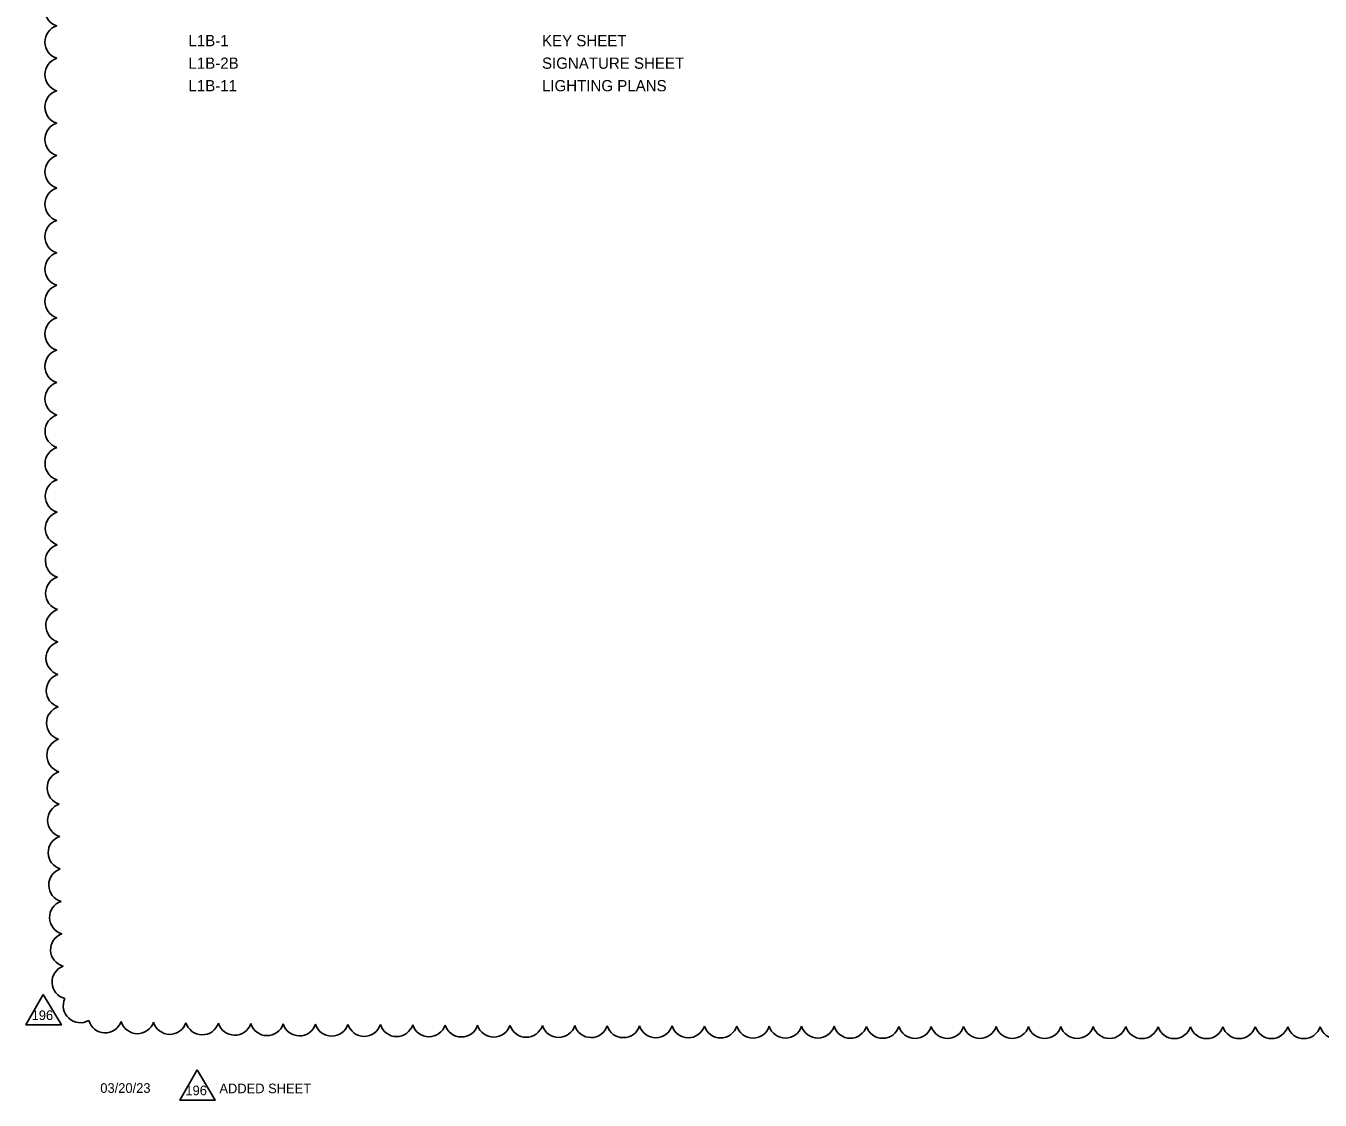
# Model space of a CAD drawing. Extents: x -811.2 to -795, y -2307.6 to -2235.1.
# Drawn here: x -811.23 to -803.18, y -2270.05 to -2263.37 of the extents above; entities that cross this region are included whole.
import ezdxf

# ---------------------------------------------------------------- set-up
doc = ezdxf.new("R2010")
doc.units = 0
for name, color, linetype in [('Cloud_dp', 7, 'Continuous'), ('TeleMisc', 7, 'Continuous'), ('TextMinor', 7, 'Continuous')]:
    doc.layers.add(name, color=color, linetype=linetype)

msp = doc.modelspace()

# ---------------------------------------------------------------- linework, layer by layer
at = {"layer": 'Cloud_dp'}
for points in [[(-811.1249, -2269.3954), (-811.2327, -2269.5835), (-811.012, -2269.5835)], [(-810.1682, -2269.8629), (-810.2759, -2270.051), (-810.0553, -2270.051)]]:
    msp.add_lwpolyline(points, close=True, dxfattribs=at)
for centre, start, end in [((-811.0086, -2263.2732), 107.45847, 252.45847), ((-811.0088, -2263.4747), 107.46563, 252.46563), ((-811.0089, -2263.6763), 107.47218, 252.47218), ((-811.009, -2263.8778), 107.47822, 252.47822), ((-811.009, -2264.0794), 107.4838, 252.4838), ((-811.0091, -2264.2809), 107.48899, 252.48899), ((-811.0091, -2264.4824), 107.49382, 252.49382), ((-811.0091, -2264.684), 107.49843, 252.49843), ((-811.0091, -2264.8855), 107.51148, 252.51148), ((-811.009, -2265.0871), 107.53101, 252.53101), ((-811.0089, -2265.2886), 107.55191, 252.55191), ((-811.0087, -2265.4901), 107.57435, 252.57435), ((-811.0084, -2265.6917), 107.59852, 252.59852), ((-811.008, -2265.8932), 107.62468, 252.62468), ((-811.0075, -2266.0947), 107.65309, 252.65309), ((-811.0069, -2266.2963), 107.68411, 252.68411), ((-811.0062, -2266.4978), 107.71817, 252.71817), ((-811.0053, -2266.6993), 107.75578, 252.75578), ((-811.0044, -2266.9009), 107.79762, 252.79762), ((-811.0032, -2267.1024), 107.84454, 252.84454), ((-811.0019, -2267.3039), 107.89767, 252.89767), ((-811.0004, -2267.5054), 107.95851, 252.95851), ((-810.9987, -2267.7069), 108.02912, 253.02912), ((-810.9967, -2267.9084), 108.11243, 253.11243), ((-810.9944, -2268.1099), 108.21279, 253.21279), ((-810.9916, -2268.3113), 108.33694, 253.33694), ((-810.9884, -2268.5128), 108.49611, 253.49611), ((-810.9845, -2268.7142), 108.71068, 253.71068), ((-810.9797, -2268.9155), 109.02298, 254.02298), ((-810.9735, -2269.1166), 109.54201, 254.54201), ((-810.9643, -2269.3173), 110.71007, 255.71007), ((-810.8945, -2269.4643), 155.06518, 300.06518), ((-810.7398, -2269.5272), 195.62937, 340.62937), ((-810.5387, -2269.5327), 196.26473, 341.26473), ((-810.3374, -2269.5365), 196.54985, 341.54985), ((-810.1359, -2269.5396), 196.72204, 341.72204), ((-809.9345, -2269.5421), 196.84059, 341.84059), ((-809.733, -2269.5443), 196.92865, 341.92865), ((-809.5315, -2269.5461), 196.99739, 341.99739), ((-809.33, -2269.5478), 197.053, 342.053), ((-809.1284, -2269.5493), 197.09919, 342.09919), ((-808.9269, -2269.5506), 197.13834, 342.13834), ((-808.7254, -2269.5519), 197.17209, 342.17209), ((-808.5239, -2269.553), 197.20158, 342.20158), ((-808.3223, -2269.554), 197.22762, 342.22762), ((-808.1208, -2269.5549), 197.25085, 342.25085), ((-807.9193, -2269.5557), 197.27174, 342.27174), ((-807.7177, -2269.5565), 197.29065, 342.29065), ((-807.5162, -2269.5572), 197.30788, 342.30788), ((-807.3146, -2269.5578), 197.32367, 342.32367), ((-807.1131, -2269.5584), 197.3382, 342.3382), ((-806.9116, -2269.559), 197.35163, 342.35163), ((-806.71, -2269.5595), 197.3641, 342.3641), ((-806.5085, -2269.5599), 197.37571, 342.37571), ((-806.3069, -2269.5604), 197.38657, 342.38657), ((-806.1054, -2269.5607), 197.39674, 342.39674), ((-805.9039, -2269.5611), 197.40629, 342.40629), ((-805.7023, -2269.5614), 197.4153, 342.4153), ((-805.5008, -2269.5617), 197.4238, 342.4238), ((-805.2992, -2269.5619), 197.43184, 342.43184), ((-805.0977, -2269.5622), 197.43947, 342.43947), ((-804.8961, -2269.5624), 197.44671, 342.44671), ((-804.6946, -2269.5625), 197.4536, 342.4536), ((-804.493, -2269.5627), 197.46017, 342.46017), ((-804.2915, -2269.5628), 197.46644, 342.46644), ((-804.09, -2269.5629), 197.47243, 342.47243), ((-803.8884, -2269.563), 197.47816, 342.47816), ((-803.6869, -2269.5631), 197.48365, 342.48365), ((-803.4853, -2269.5631), 197.48892, 342.48892), ((-803.2838, -2269.5632), 197.49398, 342.49398), ((-803.0822, -2269.5632), 197.49888, 342.49888)]:
    msp.add_arc(centre, 0.1057, start, end, dxfattribs=at)

# ---------------------------------------------------------------- texts
for p in [(-811.1971, -2269.5534), (-810.2404, -2270.0208)]:
    msp.add_text('196', height=0.05998, rotation=0, dxfattribs=at).set_placement(p)
at = {"layer": 'TeleMisc'}
for s, p in [('L1B-1', (-810.2215, -2263.5005)), ('KEY SHEET', (-808.0226, -2263.5005)), ('L1B-2B', (-810.2215, -2263.6405)), ('SIGNATURE SHEET', (-808.0226, -2263.6405)), ('L1B-11', (-810.2215, -2263.7805)), ('LIGHTING PLANS', (-808.0226, -2263.7805))]:
    msp.add_text(s, height=0.07, dxfattribs=at).set_placement(p)
at = {"layer": 'TextMinor'}
for s, p in [('03/20/23', (-810.7698, -2270.006)), ('ADDED SHEET', (-810.0291, -2270.0084))]:
    msp.add_text(s, height=0.06, dxfattribs=at).set_placement(p)

doc.saveas('drawing.dxf')
